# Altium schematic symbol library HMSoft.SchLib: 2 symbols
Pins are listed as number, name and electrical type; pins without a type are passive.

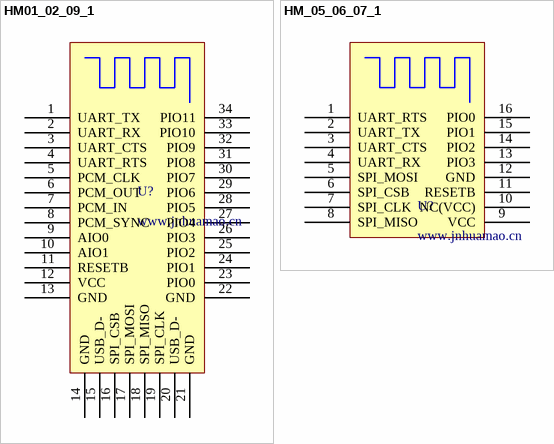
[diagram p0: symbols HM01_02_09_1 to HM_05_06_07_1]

## HM01_02_09_1
designator U?, comment www.jnhuamao.cn
HM bluetooth module HM-01,HM-02,HM-09
pins: 1 UART_TX, 2 UART_RX, 3 UART_CTS, 4 UART_RTS, 5 PCM_CLK, 6 PCM_OUT, 7 PCM_IN, 8 PCM_SYNC, 9 AIO0, 10 AIO1, 11 RESETB, 12 VCC, 13 GND, 14 GND, 15 USB_D-, 16 SPI_CSB, 17 SPI_MOSI, 18 SPI_MISO, 19 SPI_CLK, 20 USB_D-, 21 GND, 22 GND, 23 PIO0, 24 PIO1, 25 PIO2, 26 PIO3, 27 PIO4, 28 PIO5, 29 PIO6, 30 PIO7, 31 PIO8, 32 PIO9, 33 PIO10, 34 PIO11

## HM_05_06_07_1
designator U?, comment www.jnhuamao.cn
HM bluetooth module HM-05,HM-06,HM-07
pins: 1 UART_RTS, 2 UART_TX, 3 UART_CTS, 4 UART_RX, 5 SPI_MOSI, 6 SPI_CSB, 7 SPI_CLK, 8 SPI_MISO, 9 VCC, 10 NC(VCC), 11 RESETB, 12 GND, 13 PIO3, 14 PIO2, 15 PIO1, 16 PIO0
